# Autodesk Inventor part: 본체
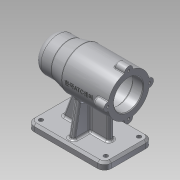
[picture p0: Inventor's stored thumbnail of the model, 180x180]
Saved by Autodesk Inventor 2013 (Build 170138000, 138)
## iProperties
Created: 2019-07
Part Number: 본체
Material: 알루미늄 6061
Document SubType Name: Modeling
Designer: Administrator
Density: 2.71 g/cm^3
Mass: 646.774 g
Surface Area: 654.083 cm^2
Volume: 238.662 cm^3
Author: Administrator
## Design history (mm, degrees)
sketch "스케치1"
  geometry: L1 (-56, 0)-(56, 0); L2 (56, 0)-(56, 21); L3 (56, 30)-(-11, 30); L4 (-11, 30)-(-31, 25); L5 (-31, 25)-(-56, 25); L6 (-56, 25)-(-56, 0); L7 (56, 21)-(41, 21); L8 (41, 21)-(41, 24); L9 (41, 24)-(-13, 24); L10 (-13, 24)-(-13, 21); L11 (-13, 21)-(-25, 21); L12 (-25, 21)-(-25, 17.5); L13 (-25, 17.5)-(-43, 17.5); L14 (-43, 17.5)-(-43, 16); L15 (-43, 16)-(-47, 16); L16 (-47, 16)-(-47, 10.5); L17 (-47, 10.5)-(-50, 10.5); L18 (-50, 10.5)-(-50, 0); L19 (56, 21)-(56, 30); 1 further point
  constraints: 38 end point, 9 horizontal, 9 vertical, 2 midpoint, 1 point on line
  dimensions: "d0" = 112 distance of L1.start L1.end; "d2" = 42 diameter of L7 L1; "d3" = 48 diameter of L9 L1; "d4" = 42 diameter of L11 L1; "d5" = 35 diameter of L13 L1; "d6" = 32 diameter of L15 L1; "d7" = 21 diameter of L17 L1; "d8" = 15 distance between parallel lines of L2 L8; "d9" = 54 distance between parallel lines of L10 L8; "d10" = 12 distance between parallel lines of L12 L10; "d11" = 18 distance between parallel lines of L14 L12; "d12" = 4 distance between parallel lines of L16 L14; "d13" = 3 distance between parallel lines of L16 L18; "d14" = 60 diameter of L3 L1; "d15" = 45 distance from line of L3.end L6; "d16" = 25 distance of L4.end L5.end; "d17" = 50 diameter of L5 L1
revolve "회전1" sketch "스케치1" stored, may be unused: angle "d18" = 90 deg
fillet "모깎기1" dims "d19" = 10, "d20" = 3, "d21" = 0.3
sketch "스케치2"
  geometry: C1 r 21 at (0, 0) reference; C2 r 6 at (0, 30)
  constraints: 1 centre point, 1 vertical alignment
  dimensions: "d22" = 30 distance of C1.centre C2.centre; "d23" = 12 diameter of C2
extrude "돌출1" join sketch "스케치2" distance "d24" = 16; taper "d25" = 0 deg
sketch "스케치3"
  geometry: A1 r 6 centre (0, 0) between (5.97, -0.6) and (-5.97, -0.6) reference; A2 r 6 centre (-30, -30) between (-29.4, -24.03) and (-29.4, -35.97) reference; A3 r 6 centre (0, -60) between (-5.97, -59.4) and (5.97, -59.4) reference; A4 r 6 centre (30, -30) between (29.4, -35.97) and (29.4, -24.03) reference; 4 further points
  constraints: 4 coincident
hole "구멍1" sketch "스케치3" at (0, 0), (-30, -30), (0, -60), (30, -30) diameter "d29" = 3.242; stored, may be unused: countersink angle "d33" = 90 deg, drill point angle "d35" = 118 deg; dims "d30" = 8, "d31" = 4, "d32" = 2, "d34" = 11
sketch "스케치4"
  geometry: L1 (-56, -70)-(56, -70); L2 (56, -70)-(56, -80); L3 (56, -80)-(-56, -80); L4 (-56, -80)-(-56, -70); 2 further points
  constraints: 8 end point, 2 parallel, 1 horizontal, 1 midpoint, 1 perpendicular, 1 vertical alignment
  dimensions: "d36" = 112 distance of L2.end L3.end; "d38" = 10 distance of L3.end L1.start; "d39" = 80 distance from line of L3 point (0, 0)
extrude "돌출2" join sketch "스케치4" stored distance "d40" = 70; taper "d41" = 0 deg
sketch "스케치5"
  geometry: L1 (0, 70)-(0, 0) reference; L2 (112, 0)-(112, 70) reference; L3 (20, 39)-(87, 39); L4 (87, 39)-(87, 31); L5 (87, 31)-(20, 31); L6 (20, 31)-(20, 39); 2 further points
  constraints: 8 end point, 2 parallel, 1 horizontal, 1 horizontal alignment, 1 midpoint, 1 perpendicular
  dimensions: "d42" = 20 distance between parallel lines of L1 L6; "d43" = 25 distance between parallel lines of L2 L4; "d44" = 8 distance of L5.end L3.start
extrude "돌출3" join sketch "스케치5" stored distance "d45" = 70; taper "d46" = 0 deg
feature "면 기울기1" dims angle "d47" = 20 deg
sketch "스케치6"
  geometry: L1 (-70, 35)-(-80, 35) reference; L2 (-70, -35)-(-70, 35) reference; L3 (-70, 28)-(-48.89, 24.278); 1 further point
  constraints: 2 end point, 1 point on line
  dimensions: "d48" = 7 distance from line of L3.start L1; "d49" = 100 deg angle of L2 L3
feature "리브1" sketch "스케치6" dims "d50" = 1, "d51" = 8, "d52" = 0, "d53" = 0, "d54" = 1, "d55" = 1
fillet "모깎기2" dims "d56" = 10
sketch "스케치7"
  geometry: A1 r 10 centre (92, -10) between (102, -10) and (92, 0) reference; A2 r 10 centre (0, -10) between (0, 0) and (-10, -10) reference; A3 r 10 centre (0, -60) between (-10, -60) and (0, -70) reference; 5 further points
  constraints: 3 coincident
hole "구멍2" sketch "스케치7" at (0, -10), (0, -60), (92, -58.141), (92, -10) diameter "d57" = 6; stored, may be unused: countersink angle "d61" = 90 deg, drill point angle "d63" = 118 deg; dims "d58" = 8, "d59" = 4, "d60" = 2, "d62" = 11
chamfer "모따기1" distance "d64" = 3; stored, may be unused: second distance "d65" = 2, angle "d66" = 45 deg
node "작업 평면1"
sketch "스케치8"
  geometry: L1 (33.5, -24)-(33.5, 24) reference; 2 further points
  constraints: 1 horizontal alignment, 1 other
  dimensions: "d67" = 42 distance from line of L1 point (-8.5, 0)
feature "엠보싱1" sketch "스케치8" dims "d0" = 112, "d2" = 42, "d3" = 48, "d4" = 42, "d5" = 35, "d6" = 32, "d7" = 21, "d8" = 15, "d9" = 54, "d10" = 12, "d11" = 18, "d12" = 4, "d13" = 3, "d14" = 60, "d15" = 45, "d16" = 25, "d17" = 50, "d68" = 0.5, "d69" = 0
fillet "모깎기4" dims "d72" = 3
fillet "모깎기5" dims "d73" = 1, "d74" = 3
chamfer "모따기2" distance "d75" = 1; stored, may be unused: second distance "d76" = 2, angle "d77" = 45 deg
node "솔리드1"
pattern_circular "원형 패턴1" dims angle "d27" = 360 deg
mirror "대칭1"
fillet "모깎기3" dims "d71" = 3
